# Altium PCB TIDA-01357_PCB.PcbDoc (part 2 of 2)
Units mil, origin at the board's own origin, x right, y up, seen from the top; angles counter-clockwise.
Board outline 1710 x 2300 mil, 4 copper layers (Top Layer, Mid Layer 1, Mid Layer 2, Bottom Layer), stack 79.8 mil thick; 69 components, 66 nets, 243 pads, 213 vias.
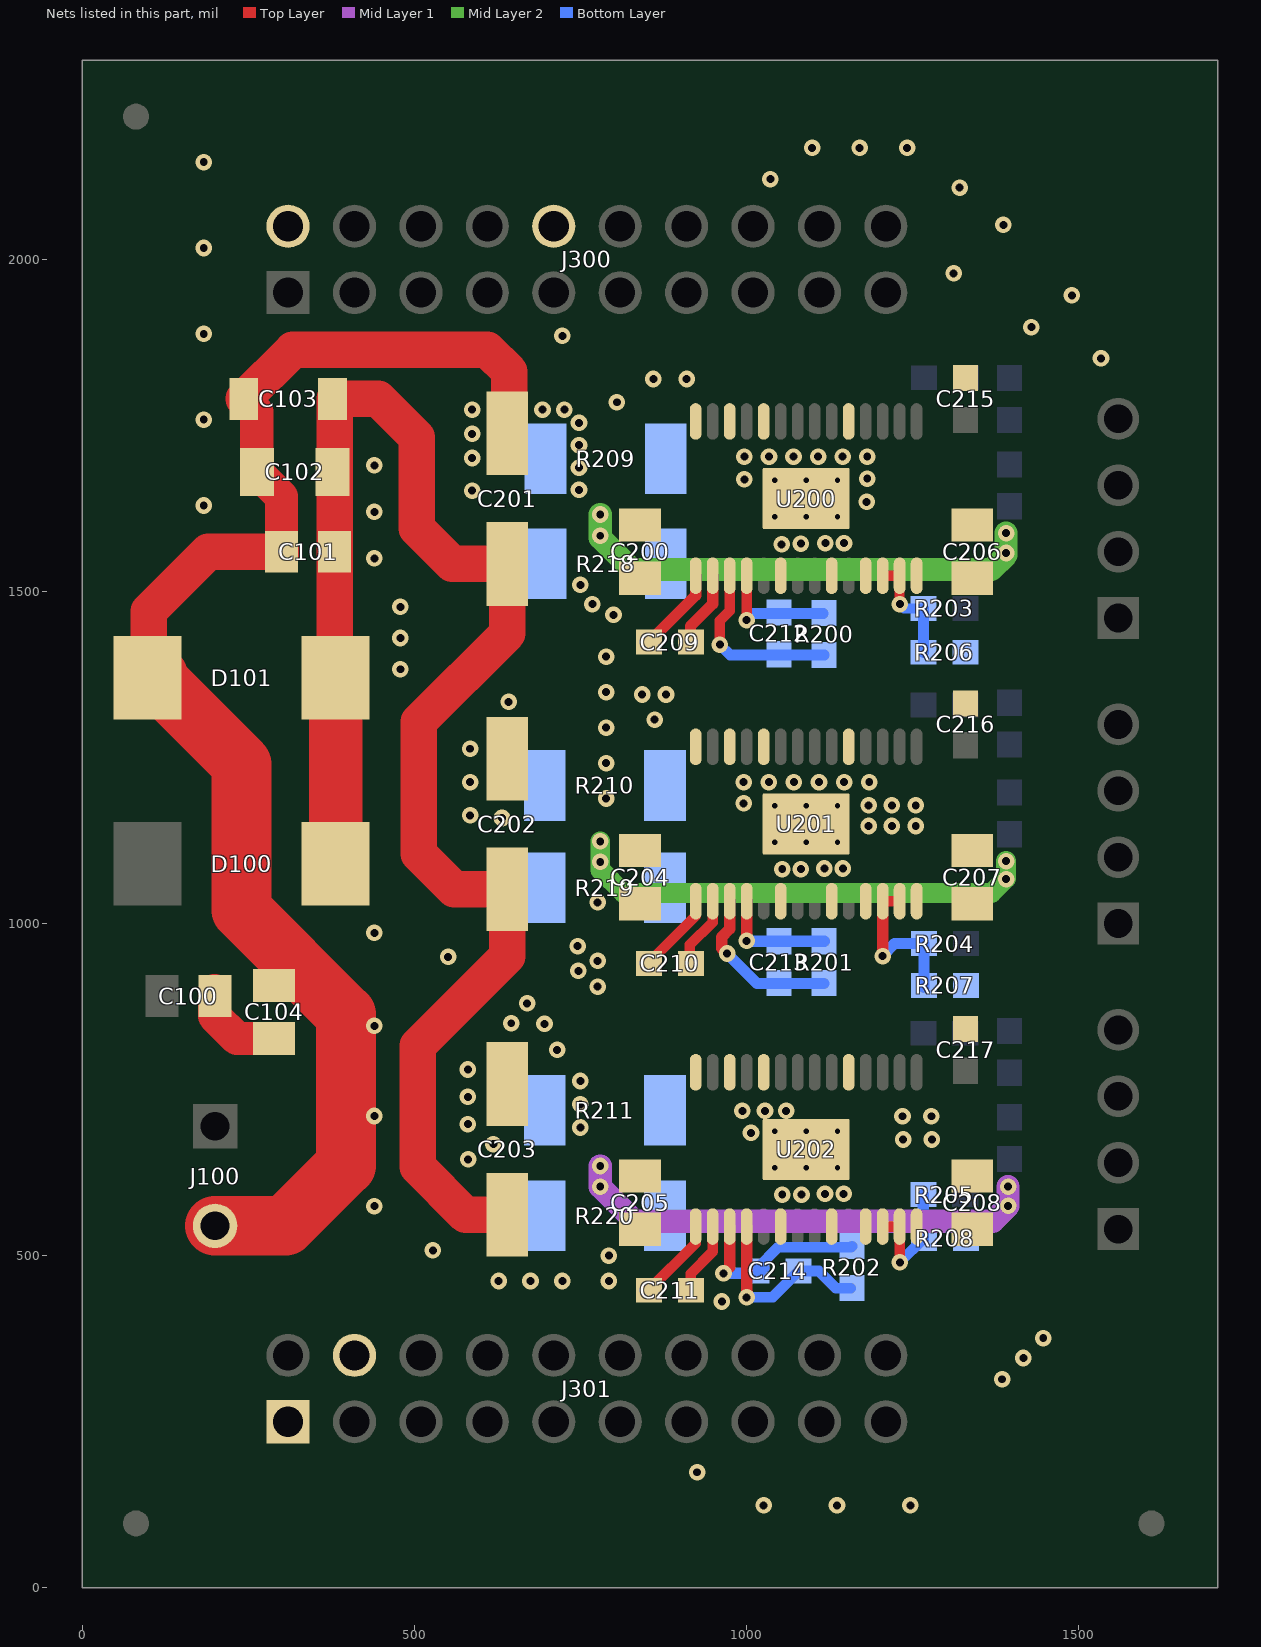
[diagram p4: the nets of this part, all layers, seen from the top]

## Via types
v1: diameter 25, hole 12, Top Layer to Bottom Layer, tented both sides, 195 vias
v2: diameter 19.68, hole 7.87, Top Layer to Bottom Layer, 18 vias

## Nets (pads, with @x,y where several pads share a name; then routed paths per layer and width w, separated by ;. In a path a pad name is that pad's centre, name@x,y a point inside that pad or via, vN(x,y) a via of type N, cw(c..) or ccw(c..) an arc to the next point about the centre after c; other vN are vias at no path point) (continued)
GND: C101.2 C102.2 C103.2 C104.2 C200.1 C201.2 C202.2 C203.2 C204.1 C205.2 C206.1 C207.1 C208.1 C215.2 C216.2 C217.2 D101.2 J100.2 J300.2 J301.4 R206.2 R207.2 R208.2 R209.2 R210.2 R211.2 R218.2 R219.2 R220.2 U200.14 U200.19 U200.24 U200.26 U200.28 U200.29 U201.14 U201.19 U201.24 U201.26 U201.28 U201.29 U202.14 U202.19 U202.24 U202.26 U202.28 U202.29 | length 2205.4
  Top Layer w50: C103.2@243.07,1790 262.91,1770.16 C102.2@262.91,1680 300,1642.91 C101.2@300,1560
  Top Layer w55: D101.2@100,1370 100,1470 190,1560 C101.2@300,1560 ; C103.2@243.07,1790 317.07,1864 610,1864 643,1831 C201.2@643,1760
  Top Layer w90: D101.2@110,1370 240,1240 240,1020 397,863 397,636 306,545 J100.2@200,545
  Top Layer w100: D101.2@98.27,1370 100,1370 D101.2@110,1370
  other v1: 1026,124 1136.5,124 1247,124 926,174 1385,314 1417,346 1447,376 963,431 627,462 675,462 723,462 793,462 793,500 528,508 440,574.67 581,645 619,668 1236,675 1279.4,675 1007,685 750,693 580.68,698 440,710.33 1235,710 1278.4,710 994,718 1028,718 1060,718 750,728 580.68,739.15 750,763 580.68,780.29 715,810 440,846 696,849 646,850 670,880 776,905 747,929 776,944 551,950 746,966 440,986 776,1032 1184,1147 1219,1147 1255,1147 632,1159 584.13,1163 1184,1178 1219,1178 1255,1178 996,1181 789,1188.32 584.13,1213.14 996,1213 1033.8,1213 1071.6,1213 1109.4,1213 1147.2,1213 1185,1213 789,1241.74 584.13,1263.29 789,1295.16 862,1307 642,1334 843,1345 879,1345 789,1348.58 479,1383 789,1402 479,1430 800,1465 479,1477 768,1481 750,1510 440,1550 440,1620 183,1629.5 1181,1635 587,1652 748,1653 997,1669 1182,1670 748,1686.67 440,1690 587,1701 997,1703 1034,1703 1071,1703 1108,1703 1145,1703 1182,1703 748,1720.33 587,1737.43 748,1754 183,1758.75 587,1773.86 693,1774 726,1773.86 805,1785 860,1820 910,1820 1534,1851 723,1885 183,1888 1429,1898 1490,1946 1312,1979 183,2017.25 1387,2052 1321,2108 1036,2121 183,2146.5 1099,2168 1170.5,2168 1242,2168
  other v2: 1042.76,632.44 1090,632.44 1137.24,632.44 1042.76,687.56 1090,687.56 1137.24,687.56 1042.76,1122.44 1090,1122.44 1137.24,1122.44 1042.76,1177.56 1090,1177.56 1137.24,1177.56 1042.76,1612.44 1090,1612.44 1137.24,1612.44 1042.76,1667.56 1090,1667.56 1137.24,1667.56
LP_+3V3: J301.1
LP_RESET: J300.10
NetC100_2: C100.2 C104.1 | length 142.1
  Top Layer w50: C100.2@199,899 199,861 233,827 C104.1@289,827
NetC209_1: C209.1 U200.1 | length 128.9
  Top Layer w17: C209.1@853.5,1424 923.66,1494.16 U200.1@923.66,1523.86
NetC209_2: C209.2 U200.2 | length 113.6
  Top Layer w17: C209.2@916,1424 916,1448 949.25,1481.25 U200.2@949.25,1523.86
NetC210_1: C210.1 U201.1 | length 122.1
  Top Layer w16: C210.1@853,941 923.66,1011.66 U201.1@923.66,1033.86
NetC210_2: C210.2 U201.2 | length 110
  Top Layer w16: C210.2@915,938 915,968 949.25,1002.25 U201.2@949.25,1033.86
NetC211_1: C211.1 U202.1 | length 126.5
  Top Layer w16: C211.1@852,447 923.66,518.66 U202.1@923.66,543.86
NetC211_2: C211.2 U202.2 | length 110.6
  Top Layer w16: C211.2@916,447 916,473 949.25,506.25 U202.2@949.25,543.86
NetC212_2: C212.2 R200.1 U200.3 | length 273.4
  Top Layer w16: v1(960,1420) 960,1456 974.84,1470.84 U200.3@974.84,1523.86
  Bottom Layer w16: v1(960,1420) 975.5,1404.5 R200.1@1117,1404.5
NetC213_2: C213.2 R201.1 U201.3 | length 252
  Top Layer w17: v1(971,955) 963,963 963,980 974.84,991.84 U201.3@974.84,1033.86
  Bottom Layer w6: R201.1@1116.56,910 R201.1@1117.07,910.5
  Bottom Layer w17: v1(971,955) 1016,910 R201.1@1116.56,910
NetC214_2: C214.2 R202.1 U202.3 | length 299.6
  Top Layer w17: v1(965.5,473.5) 974.84,482.84 U202.3@974.84,543.86
  Bottom Layer w16: C214.2@1015.5,477 1015.5,480.5 1048,513 1157.5,513 R202.1@1159,514.5
  Bottom Layer w17: v1(965.5,473.5) 1018.5,473.5 C214.2@1026.5,481.5
NetR203_2: R203.2 R206.1 U200.12 U200.13 | length 172.9
  Top Layer w15: v1@1230.75,1481 U200.13@1230.75,1523.86
  Top Layer w16: U200.12@1205.16,1523.86 U200.13@1230.75,1523.86
  Bottom Layer w15: v1(1231,1481) 1237.46,1474.54 R203.2@1266.75,1474.54
  Bottom Layer w17: R206.1@1266.75,1408.54 R203.2@1266.75,1474.54
NetR204_2: R204.2 R207.1 U201.12 U201.13 | length 245.2
  Top Layer w16: U201.12@1205.16,1033.86 U201.13@1230.75,1033.86
  Top Layer w17: v1(1205.16,951) U201.12@1205.16,1033.86
  Bottom Layer w6: R204.2@1267.35,970.16 R204.2@1267.5,970
  Bottom Layer w17: v1@1204.5,951.5 1223.16,970.16 R204.2@1267.35,970.16 ; R207.1@1267.5,904 R204.2@1267.5,970
NetR205_2: R205.2 R208.1 U202.12 U202.13 | length 196.6
  Top Layer w6: v1@1230.75,490.25 v1(1231,490)
  Top Layer w16: U202.12@1205.16,543.86 U202.13@1230.75,543.86 v1@1230.75,490.25
  Bottom Layer w6: R208.1@1266,525 R208.1@1266.5,525
  Bottom Layer w16: v1(1231,490) R208.1@1266,525
  Bottom Layer w17: R208.1@1266.5,525 R205.2@1266.5,592
NetR209_1: R209.1 U200.6
  other v1: 1053,1571 1082,1572
NetR210_1: R210.1 U201.6
  other v1: 1054,1082 1082,1082
NetR211_1: R211.1 U202.6
  other v1: 1054,592 1083,592
NetR218_1: R218.1 U200.9
  other v1: 1119,1573 1147,1573
NetR219_1: R219.1 U201.9
  other v1: 1117.38,1083 1145.38,1083
NetR220_1: R220.1 U202.9
  other v1: 1118.38,593 1146.38,593
V_SUPPLY: C101.1 C102.1 C103.1 C200.2 C201.1 C202.1 C203.1 C204.2 C205.1 C206.2 C207.2 C208.2 C212.1 C213.1 C214.1 D100.1 D101.1 R200.2 R201.2 R202.2 U200.4 U200.11 U201.4 U201.11 U202.4 U202.11 | length 5198.8
  Top Layer w6: C103.1@376.93,1790 C103.1@380,1790 ; C202.1@614.43,1051.57 C202.1@640,1051.57
  Top Layer w16: v1(1000.43,1457) U200.4@1000.43,1523.86
  Top Layer w17: v1(1000.43,437.43) U202.4@1000.43,543.86 ; v1(1000.43,974) U201.4@1000.43,1033.86
  Top Layer w55: D101.1@380,1370 C101.1@380,1560 380,1790 446,1790 504,1732 504,1595 557.43,1541.57 C201.1@640,1541.57 640,1437 507,1304 507,1105 560.43,1051.57 C202.1@614.43,1051.57 ; 505,634 577.43,561.57 C203.1@640,561.57 ; 505,637 505,816 640,951 C202.1@640,1051.57
  Top Layer w80: D100.1@381.73,1090 D101.1@381.73,1370
  Mid Layer 1 w35: v1(780,635) v1(780,604) 832,552 1371,552 v1(1394,575) v1(1394,604)
  Mid Layer 2 w30: v1(780,1124) v1(780,1093) 780,1081 815,1046 1369,1046 1391,1068 v1(1391,1094) ; v1@780,1581 v1(780,1584) ; v1@1391,1555 v1(1391,1558)
  Mid Layer 2 w35: v1@780,1581 828,1533 1369,1533 v1@1391,1555 ; v1(780,1584) v1(780,1616) ; v1(1391,1558) v1(1391,1588)
  Bottom Layer w16: v1(1000.43,437.43) 1039.43,437.43 1079,477 1109,477 1135,451 R202.2@1157,451 ; v1(1000.43,1457) 1010.43,1467 R200.2@1116,1467
  Bottom Layer w17: v1@1000,973.5 R201.2@1117.07,973.5
  other v1: 1391,1067
pads on no net: FID1.1 FID2.1 FID3.1 J300.12 J300.14 J301.2 J301.3 J301.5 J301.6 J301.7 J301.8 J301.10 J301.11 J301.12 J301.14 J301.16 J301.18 J301.20 LBL1.0

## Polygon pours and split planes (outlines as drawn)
GND on Top Layer "Top Layer-No Net 1" (solid, remove dead copper, pour order 46): 0,0 1710,0 1710,2300 0,2300 0,0
NetR220_1 on Top Layer "TOP_LAYER_NETR220_1_P026" (solid, remove dead copper, pour order 26): 1118,516 1139.38,516 1139.38,573 1145.38,579 1159.38,579 1161.38,581 1161.38,602 1157.38,606 1102.38,606 1102.38,586 1118,570.38
NetR219_1 on Top Layer "TOP_LAYER_NETR219_1_P024" (solid, remove dead copper, pour order 24): 1117,1006 1138.38,1006 1138.38,1063 1144.38,1069 1158.38,1069 1160.38,1071 1160.38,1092 1156.38,1096 1101.38,1096 1101.38,1076 1117,1060.38
NetR218_1 on Top Layer "TOP_LAYER_NETR218_1_P020" (solid, remove dead copper, pour order 20): 1119,1496 1140,1496 1140,1553 1146,1559 1160,1559 1162,1561 1162,1582 1157,1587 1103,1587 1103,1566 1119,1550 1119,1540
NetR211_1 on Top Layer "Top Layer-No Net" (solid, remove dead copper, pour order 18): 1040.15,517 1062.15,517 1062.15,575 1066.15,579 1091,579 1097,585 1097,600 1091,606 1044.15,606 1040.15,602
NetR210_1 on Top Layer "Top Layer-No Net" (solid, remove dead copper, pour order 16): 1040.15,1007 1062.15,1007 1062.15,1065 1066.15,1069 1090,1069 1096,1075 1096,1090 1090,1096 1044.15,1096 1040.15,1092
NetR209_1 on Top Layer "Top Layer-No Net" (solid, remove dead copper, pour order 14): 1040,1496 1062,1496 1062,1551 1070,1559 1091,1559 1096,1564 1096,1581 1091,1586 1045,1586 1040,1581
V_SUPPLY on Top Layer "TOP_LAYER_V_SUPPLY_P000" (solid, remove dead copper, pour order 0): 1170,1500 1180,1500 1190,1500 1190,1550 1210,1570 1360,1570 1380,1550 1390,1540 1400,1540 1410,1550 1410,1600 1390,1630 1290,1630 1270,1610 1200,1610 1170,1580
V_SUPPLY on Top Layer "TOP_LAYER_V_SUPPLY_P002" (solid, pour order 2): 990,1500 1010,1500 1010,1560 1010,1580 990,1600 980,1610 907.24,1610 887.24,1630 690,1630 670,1610 610,1610 600,1600 600,1480 610,1470 670,1470 680,1480 680,1540 710,1570 970,1570 990,1550 990,1500
V_SUPPLY on Top Layer "TOP_LAYER_V_SUPPLY_P004" (solid, remove dead copper, pour order 4): 990,1010 1010,1010 1010,1070 1010,1090 990,1110 980,1120 907.24,1120 887.24,1140 690,1140 670,1120 610,1120 600,1110 600,990 610,980 670,980 680,990 680,1050 710,1080 970,1080 990,1060 990,1010
V_SUPPLY on Top Layer "TOP_LAYER_V_SUPPLY_P006" (solid, remove dead copper, pour order 6): 1170,1010 1180,1010 1190,1010 1190,1060 1210,1080 1360,1080 1390,1050 1400,1050 1410,1060 1410,1110 1390,1140 1290,1140 1270,1120 1200,1120 1170,1090
V_SUPPLY on Top Layer "TOP_LAYER_V_SUPPLY_P008" (solid, remove dead copper, pour order 8): 1170,520 1180,520 1190,520 1190,570 1210,590 1360,590 1390,560 1400,560 1410,570 1410,610 1390,650 1290,650 1270,630 1200,630 1170,600
V_SUPPLY on Top Layer "TOP_LAYER_V_SUPPLY_P010" (solid, remove dead copper, pour order 10): 990,520 1010,520 1010,580 1010,600 990,620 980,630 907.24,630 887.24,650 690,650 670,630 610,630 600,620 600,500 610,490 670,490 680,500 680,560 710,590 970,590 990,570 990,520
GND on Bottom Layer "Top Layer-No Net 1" (solid, remove dead copper, pour order 48): 0,0 1710,0 1710,2300 0,2300 0,0
NetR218_1 on Bottom Layer "BOTTOM_LAYER_NETR218_1_P030" (solid, remove dead copper, pour order 30): 1110,1590 1160,1590 1170,1580 1170,1560 1120,1510 1006,1510 976,1480 850,1480 840,1490 840,1590 840,1591 850,1601 949,1601 1007,1543 1092,1543 1100,1551 1100,1580
NetR209_1 on Bottom Layer "BOTTOM_LAYER_NETR209_1_P028" (solid, remove dead copper, pour order 28): 1036,1593 1083,1593 1096,1580 1096,1565 1083,1552 1014,1552 936,1630 850,1630 840,1640 840,1750 850,1760 930.11,1760 960,1729.78 960,1669
NetR210_1 on Bottom Layer "BOTTOM_LAYER_NETR210_1_P032" (solid, remove dead copper, pour order 32): 1036,1103 1083,1103 1096,1090 1096,1075 1083,1062 1014,1062 936,1140 850,1140 840,1150 840,1260 850,1270 930.11,1270 960,1239.78 960,1179
NetR219_1 on Bottom Layer "BOTTOM_LAYER_NETR219_1_P034" (solid, remove dead copper, pour order 34): 1108.38,1100 1158.38,1100 1168.38,1090 1168.38,1070 1118.38,1020 1004.38,1020 974.38,990 848.38,990 838.38,1000 838.38,1100 838.38,1101 848.38,1111 947.38,1111 1005.38,1053 1090.38,1053 1098.38,1061 1098.38,1090
NetR211_1 on Bottom Layer "BOTTOM_LAYER_NETR211_1_P038" (solid, remove dead copper, pour order 38): 1037,613 1084,613 1097,600 1097,585 1084,572 1015,572 937,650 851,650 841,660 841,770 851,780 931.11,780 961,749.78 961,689
NetR220_1 on Bottom Layer "BOTTOM_LAYER_NETR220_1_P040" (solid, remove dead copper, pour order 40): 1109.38,610 1159.38,610 1169.38,600 1169.38,580 1119.38,530 1005.38,530 975.38,500 849.38,500 839.38,510 839.38,610 839.38,611 849.38,621 948.38,621 1006.38,563 1091.38,563 1099.38,571 1099.38,600

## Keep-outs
Keep-Out Layer:
  text ".Layer_Name" at -1713,-1458.49 h60

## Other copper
Top Layer:
  text ".Layer_Name" at -1713,-1458.49 h60
Bottom Layer:
  text ".Layer_Name" at -1713,-1458.49 h60

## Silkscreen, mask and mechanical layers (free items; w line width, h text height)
Top Overlay:
  region: 1659,2237 1359,2237 1359,2137 1659,2137
  text "TIDA-01357 PCB_Rev-E1" at 231,2171 h40
  text ".Layer_Name" at -1713,-1458.49 h60
Bottom Overlay:
  text ".Layer_Name" at -1713,-1458.49 h60
Top Paste:
  text ".Layer_Name" at -1713,-1458.49 h60
Bottom Paste:
  text ".Layer_Name" at -1713,-1458.49 h60
Top Solder:
  text ".Layer_Name" at -1713,-1458.49 h60
  text ".Layer_Name" at -1713,-1458.49 h60
Bottom Solder:
  text ".Layer_Name" at -1713,-1458.49 h60
Drill Guide:
  text ".Layer_Name" at -1713,-1458.49 h60
M1 Board Outline:
  the board outline again, w10
  text ".Layer_Name" at -1713,-1458.49 h60
M2 Board Dimensions:
  rectangle: -2290,-875 -2165,-750
  rectangle: -2165,-1000 -1790,-875
  lines w7: -2290,-875 -1290,-875 ; -2165,-1000 -2165,-750 ; -2040,-1000 -2040,-750 ; -1790,-1000 -1790,-750 ; -1540,-1000 -1540,-750 ; -2290,-1000 -1290,-1000 -1290,-750 -2290,-750 -2290,-1000
  text ".Layer_Name" at -1713,-1458.49 h60
M3 3D STEP Top:
  text ".Layer_Name" at -1713,-1458.49 h60
M4 3D STEP Bottom:
  text ".Layer_Name" at -1713,-1458.49 h60
M5 Assembly Top:
  lines w10: -2582,-1530.17 4018,-1530.17 ; -2582,-1326.83 4020,-1326.83 ; -2582,-1123.5 -2582,-1733.5 1423,-1733.5 4020,-1733.5 4020,-1123.5 -2581.5,-1123.5 -2581.5,-1733.5 -1006,-1733.5 ; -117,-1733.5 -117,-1123.5 ; 1150,-1326.83 1150,-1123.5 ; 1990,-1326.83 1990,-1123.5 ; 2612,-1740 2612,-1537.17
  text "COMPONENTS MARKED 'DNP' SHOULD NOT BE POPULATED." at -1136.5,-918.5 h60
  text "ASSEMBLY VARIANT:" at -1137,-1034 h60
  text ".VariantName" at -101,-1034 h60
  text "PCB VIEWED FROM TOP SIDE" at -2518.5,-1255.67 h60
  text "BOARD #:" at -42,-1255.67 h60
  text ".PRJ_Number" at 503.5,-1255.67 h60
  text "REV:" at 1348,-1255.67 h60
  text ".PCB_Rev" at 1639.5,-1255.67 h60
  text "SVN REV:" at 2186,-1255.67 h60
  text ".VersionControl_RevNumber" at 2692,-1255.67 h60
  text "TID #:" at -42,-1459 h60
  text ".TID" at 503.5,-1459 h60
  text "PLOT NAME =" at -2518.5,-1664.34 h60
  text ".plot_File_Name" at -1713,-1664.34 h60
  text "GENERATED    :" at -40,-1664.34 h60
  text ".Print_Date" at 829.5,-1664.34 h60
  text ".Print_Time" at 1558.5,-1664.34 h60
  text "TEXAS INSTRUMENTS" at 2823,-1664.34 h60
M6 Assembly Bottom:
  lines w10: -2582.5,-1327.33 4019.5,-1327.33 ; -2580.5,-1530.67 4019.5,-1530.67 ; -1174.5,-1740.5 -1174.5,-1537.67 ; -552.5,-1327.33 -552.5,-1124 ; 287.5,-1327.33 287.5,-1124 ; 1554.5,-1734 1554.5,-1124 ; 2443.5,-1734 4019,-1734 4019,-1124 -2582.5,-1124 -2582.5,-1734 14.5,-1734 4019.5,-1734 4019.5,-1124
  text "COMPONENTS MARKED 'DNP' SHOULD NOT BE POPULATED." at 3812,-918 h60
  text ".VariantName" at 2768,-1034 h60
  text "ASSEMBLY VARIANT:" at 3807,-1034 h60
  text ".VersionControl_RevNumber" at -1254.5,-1256.17 h60
  text "SVN REV:" at -748.5,-1256.17 h60
  text ".PCB_Rev" at -202,-1256.17 h60
  text "REV:" at 89.5,-1256.17 h60
  text ".PRJ_Number" at 934,-1256.17 h60
  text "BOARD #:" at 1479.5,-1256.17 h60
  text "PCB VIEWED FROM BOTTOM SIDE" at 3956,-1256.17 h60
  text ".TID" at 934,-1459.5 h60
  text "TID #:" at 1479.5,-1459.5 h60
  text "TEXAS INSTRUMENTS" at -1385.5,-1664.84 h60
  text ".Print_Time" at -121,-1664.84 h60
  text ".Print_Date" at 608,-1664.84 h60
  text "GENERATED    :" at 1477.5,-1664.84 h60
  text ".plot_File_Name" at 3150.5,-1664.84 h60
  text "PLOT NAME =" at 3956,-1664.84 h60
M9 Title Sheet:
  drawing of 57 lines, arcs and shapes, not listed
  text "1" at -1550.16,7436.5 h70
  text "2" at 945.5,7436.5 h70
  text "3" at 3434.84,7436.5 h70
  text "4" at 5941.51,7436.5 h70
  text "5" at 8440.5,7436.5 h70
  text "6" at 10945.5,7436.5 h70
  text "A" at -2706.5,6293.5 h70
  text "A" at 12093.5,6293.5 h70
  text "B" at -2706.5,3913.5 h70
  text "B" at 12093.5,3913.5 h70
  text "C" at -2706.5,1538.5 h70
  text "C" at 12093.5,1538.5 h70
  text "PROJECT TITLE:" at 9053.5,-322.5 h45
  text ".PRJ_Title" at 9103.5,-455.83 h70
  text "DESIGNED FOR:" at 9053.5,-623.5 h45
  text ".PRJ_Customer" at 9103.5,-763.5 h70
  text "D" at -2706.5,-831.5 h70
  text "D" at 12093.5,-831.5 h70
  text "FILE NAME:" at 9053.5,-923.5 h45
  text ".PCB_File_Name_No_Path" at 9103.5,-1043.5 h70
  text "Texas Instruments (TI) and/or its licensors do not warrant the accuracy or completeness of this specification" at 4084,-1205.34 h45
  text "ENGINEER:" at 9053.5,-1213.5 h45
  text "LAYOUT BY:" at 10558.5,-1213.5 h45
  text "or any information contained therein. TI and/or its licensors do not warrant that this design will meet" at 4039.01,-1318 h45
  text ".PRJ_Engineer" at 9103.5,-1368.49 h70
  text ".PCB_Layout" at 10609,-1368.49 h70
  text "the specifications, will be suitable for your application or fit for any particular purpose, or will operate in" at 4039.01,-1430.67 h45
  text ".Layer_Name" at -1713,-1458.49 h60
  text "ALTIUM DESIGNER VERSION:" at 10558.5,-1523.5 h45
  text "an implementation. TI and/or its licensors do not warrant that the design is production worthy. You should" at 4039.01,-1543.33 h45
  text "completely validate and test your design implementation to confirm the system functionality for your application." at 4084,-1656 h45
  text ".print_Scale" at 9103.5,-1656.83 h70
  text ".Application_BuildNumber" at 10609,-1656.83 h70
  text "1" at -1550.16,-1863.5 h70
  text "2" at 945.5,-1863.5 h70
  text "3" at 3434.84,-1863.5 h70
  text "4" at 5941.51,-1863.5 h70
  text "5" at 8440.5,-1863.5 h70
  text "6" at 10945.5,-1863.5 h70
M10 Fab Notes:
  drawing of 173 lines, arcs and shapes, not listed
  text "DESIGN INFORMATION" at 10088.02,5601 h60
  text "MIN. TRACK WIDTH:" at 9443.46,5421 h60
  text "8" at 10539.7,5421 h60
  text "MIL" at 10694.46,5421 h60
  text "MIN. CLEARANCE:" at 9443.46,5289 h60
  text "0.2" at 10479.7,5289 h60
  text "mm" at 10694.46,5289 h60
  text "MIN. VIA PAD SIZE:" at 9443.46,5157 h60
  text "24" at 10509.71,5157 h60
  text "MIL" at 10694.46,5157 h60
  text "0.05mm (2MIL)" at 10138.46,5015.29 h60
  text "MINIMUM ANNULAR RING" at 9114.23,5011 h60
  text "EXTERNAL" at 10846.46,5011 h60
  text "PER" at 9314.23,4893 h60
  text "IPC-D-275 CLASS 2 LEVEL C" at 9534.23,4893 h60
  text "MIL, HOLES" at 11022.46,4780.71 h60
  text "+/-" at 10630,4780 h60
  text "+/-" at 11484,4780 h60
  text "REGISTRATION TOLERANCES:" at 9114.23,4775 h60
  text "METAL" at 10314,4775 h60
  text "5" at 10890.2,4775 h60
  text "3" at 11723.2,4775 h60
  text "MIL" at 11839.46,4775 h60
  text "+/-" at 11484,4662 h60
  text "HOLE SIZE TOLERANCE (UNLESS OTHERWISE SPECIFIED):" at 9114.23,4657 h60
  text "3" at 11723.2,4657 h60
  text "MIL" at 11839.46,4657 h60
  text "MATERIAL:" at 9039.46,4447.54 h60
  text "FR-4 High Tg" at 10025.9,4307.21 h60
  text "FR-408" at 9460.46,4298.64 h60
  text "OTHER" at 10948.46,4298.64 h60
  text "X" at 9871,4295 h60
  text "62 MIL (1.6mm) +/-10%" at 9780.56,4135.92 h60
  text "THICKNESS:" at 9114.23,4131.64 h60
  text "X" at 9652.4,4131.64 h60
  text "OTHER" at 11065.46,4131.64 h60
  text "TOLERANCE:" at 9114.23,3973.64 h60
  text "X" at 9953.53,3973.64 h60
  text "ANSI IPC-6012 TYPE 3 CLASS 2" at 10140.48,3973.64 h60
  text "OTHER +/-" at 10140.46,3817.64 h60
  text "BOW & TWIST:" at 9114.23,3660.64 h60
  text "X" at 9953.53,3660.64 h60
  text "ANSI IPC-6012 TYPE 3 CLASS 2" at 10140.48,3660.64 h60
  text "OTHER +/-" at 10140.46,3502.13 h60
  text "DRILLING:" at 9039.46,3363.64 h60
  text "REFERENCE:" at 9114.23,3246.64 h60
  text "X" at 9762.46,3246.64 h60
  text "AS SHOWN" at 9949.46,3246.64 h60
  text "X" at 10663.46,3246.64 h60
  text "NC_DRILL FILES" at 10800.46,3246.64 h60
  text "PTH COPPER THICKNESS:" at 9114.23,3088.64 h60
  text "X" at 10244.46,3088.64 h60
  text "20-30 um" at 10381.46,3088.64 h60
  text "OTHER" at 11098.46,3088.64 h60
  text "BOARD FINISH:" at 9039.46,2929.64 h60
  text "SILKSCREEN:" at 9194.68,2811.64 h60
  text "X" at 10143.46,2811.64 h60
  text "TOP" at 10269.46,2811.64 h60
  text "X" at 10653.46,2811.64 h60
  text "BOTTOM" at 10780.46,2811.64 h60
  text "SILKSCREEN COLOR:" at 9194.68,2644.64 h60
  text "X" at 10142.42,2644.64 h60
  text "WHITE" at 10269.46,2644.64 h60
  text "OTHER" at 10780.46,2644.64 h60
  text "X" at 10273.42,2485.44 h60
  text "GREEN" at 10400.46,2485.44 h60
  text "OTHER" at 11018.46,2485.44 h60
  text "SOLDER RESIST COLOR:" at 9194.68,2474.64 h60
  text "X" at 10273.42,2315.44 h60
  text "MATTE" at 10400.46,2315.44 h60
  text "SEMI-GLOSS" at 11018,2314.8 h60
  text "IMMERSION GOLD (ENIG)" at 10100.46,2126.92 h60
  text "ENEPIG" at 11438,2123.64 h60
  text "SURFACE FINISH:" at 9039.46,2122.64 h60
  text "X" at 9913.51,2122.64 h60
  text "IMM. TIN/SILVER OR EQUIV" at 9369,1965.64 h60
  text "OTHER" at 10800.46,1965.64 h60
  text "ARRAY/PANEL:" at 9039.46,1786.64 h60
  text "CUT AND TRIM PER M1 BOARD OUTLINE" at 10100.46,1782.35 h60
  text "N.C. ROUTE" at 10100.46,1630.64 h60
  text "X" at 10779.46,1630.64 h60
  text "V. SCORE" at 10966.46,1630.64 h60
  text "CERTIFICATION:" at 9039.46,1493.64 h60
  text "MATERIALS AND WORKMANSHIP FOR ALL PCBS" at 9764.46,1493.64 h60
  text "TO MEET OR EXCEED THE REQUIREMENTS OF:" at 9764.46,1395.64 h60
  text "X" at 9390.96,1259.13 h60
  text "ANSI IPC-A-600F CLASS ->" at 9529.96,1259.13 h60
  text "X" at 11169.02,1259.13 h60
  text "2" at 11287.96,1259.14 h60
  text "1" at 10972.96,1257.64 h60
  text "3" at 11641.96,1257.64 h60
  text "X" at 10205.02,1099.64 h60
  text "RoHS" at 10341.96,1099.64 h60
  text "OTHER" at 10986.36,1099.64 h60
  text "PER ORDER" at 11383.42,1099.64 h60
  text "ALL BOARDS MUST MEET OR EXCEED UL94-V0 REQUIREMENTS." at 9067,934 h60
  text "PCB MUST BEAR THE UL94V-0 UL REGISTERED MATERIAL ID NUMBER" at 9067,814 h60
  text "ADDITIONAL REQUIREMENTS:" at 9039.46,640.64 h60
  text "MICROSECTION:" at 9114.23,525.64 h60
  text "YES" at 10019.96,525.64 h60
  text "REQUIRED" at 10881.46,369.49 h60
  text "BARE BOARD ELEC. TEST:" at 9114.23,366.64 h60
  text "NONE" at 10419.96,366.64 h60
  text "X" at 10754.46,366.64 h60
  text "PER ORDER" at 11473.46,366.64 h60
  text ".Layer_Name" at -1713,-1458.49 h60
M11 Gerber Information:
  lines w10: -2582,-1530.17 4018,-1530.17 ; -2582,-1326.83 4020,-1326.83 ; -2582,-1123.5 -2582,-1733.5 1423,-1733.5 4020,-1733.5 4020,-1123.5 -2581.5,-1123.5 -2581.5,-1733.5 -1006,-1733.5 ; -117,-1733.5 -117,-1123.5 ; 1150,-1326.83 1150,-1123.5 ; 1990,-1326.83 1990,-1123.5 ; 2612,-1740 2612,-1537.17
  text "ALL ARTWORK VIEWED FROM TOP SIDE" at -2518.5,-1255.67 h60
  text "BOARD #:" at -42,-1255.67 h60
  text ".PRJ_Number" at 503.5,-1255.67 h60
  text "REV:" at 1348,-1255.67 h60
  text ".PCB_Rev" at 1639.5,-1255.67 h60
  text "SVN REV:" at 2186,-1255.67 h60
  text ".VersionControl_RevNumber" at 2692,-1255.67 h60
  text "LAYER NAME =" at -2518.5,-1458.49 h60
  text "TID #:" at -42,-1459 h60
  text ".TID" at 503.5,-1459 h60
  text "PLOT NAME =" at -2518.5,-1664.34 h60
  text ".plot_File_Name" at -1713,-1664.34 h60
  text "GENERATED    :" at -40,-1664.34 h60
  text ".Print_Date" at 829.5,-1664.34 h60
  text ".Print_Time" at 1558.5,-1664.34 h60
  text "TEXAS INSTRUMENTS" at 2823,-1664.34 h60
M12 Stackup:
  drawing of 191 lines, arcs and shapes, not listed
  text "Layer" at 7500.34,7230 h60
  text "Name" at 7910.26,7230 h60
  text "Material" at 8840,7230 h60
  text "Thickness" at 9699.77,7230 h60
  text "Constant" at 10349.6,7230 h60
  text "Board Layer Stack" at 10919.46,7230 h60
  text "1" at 7500.34,7110 h60
  text "Top Overlay" at 7910.26,7110 h60
  text "2" at 7500.34,6990 h60
  text "Top Solder" at 7910.26,6990 h60
  text "Solder Resist" at 8840,6990 h60
  text "0.40mil" at 9699.77,6990 h60
  text "3.5" at 10349.6,6990 h60
  text "3" at 7500.34,6870 h60
  text "Top Layer" at 7910.26,6870 h60
  text "Copper" at 8840,6870 h60
  text "1.40mil" at 9699.77,6870 h60
  text "4" at 7500.34,6750 h60
  text "Dielectric1" at 7910.26,6750 h60
  text "FR-4" at 8840,6750 h60
  text "59.20mil" at 9699.77,6750 h60
  text "4.8" at 10349.6,6750 h60
  text "5" at 7500.34,6630 h60
  text "Bottom Layer" at 7910.26,6630 h60
  text "Copper" at 8840,6630 h60
  text "1.40mil" at 9699.77,6630 h60
  text "6" at 7500.34,6510 h60
  text "Bottom Solder" at 7910.26,6510 h60
  text "Solder Resist" at 8840,6510 h60
  text "0.40mil" at 9699.77,6510 h60
  text "3.5" at 10349.6,6510 h60
  text "7" at 7500.34,6390 h60
  text "Bottom Overlay" at 7910.26,6390 h60
  text ".Layer_Name" at -1713,-1458.49 h60
M13 Component Bodies Top:
  text ".Layer_Name" at -1713,-1458.49 h60
M14 Component Bodies Bottom:
  text ".Layer_Name" at -1713,-1458.49 h60
M15 Courtyards Top:
  text ".Layer_Name" at -1713,-1458.49 h60
M16 Courtyards Bottom:
  text ".Layer_Name" at -1713,-1458.49 h60
Drill Drawing:
  circle w10: c3058.9,2603.16 r13.28
  circle w10: c3058.9,2603.16 r22.14
  lines w10: 3036.76,2392.84 3047.83,2392.84 3047.83,2381.77 3069.97,2381.77 3069.97,2392.84 3081.04,2392.84 3081.04,2414.98 3069.97,2414.98 3069.97,2426.05 3047.83,2426.05 3047.83,2414.98 3036.76,2414.98 3036.76,2392.84 ; 3036.76,2481.4 3081.04,2481.4 3081.04,2525.67 3036.76,2525.67 3036.76,2481.4 ; 3036.76,2724.92 3081.04,2724.92 3058.9,2680.64 3036.76,2724.92
  lines w12: 2996,2351.89 6108.94,2351.89 ; 2996,2750.38 6108.94,2750.38 ; 3311.63,2252.27 3311.63,2850 ; 3628.82,2252.27 3628.82,2850 ; 4250.56,2252.27 4250.56,2850 ; 4494.88,2252.27 4494.88,2850 ; 4855.22,2252.27 4855.22,2850 ; 5564.73,2252.27 5564.73,2850 ; 2996,2252.27 6108.94,2252.27 6108.94,2850 2996,2850 2996,2252.27
  text "Symbol" at 3055.77,2780.26 h72
  text "Quantity" at 3341.52,2780.26 h72
  text "Finished Hole Size" at 3658.7,2780.26 h72
  text "Plated" at 4280.45,2780.26 h72
  text "Hole Type" at 4524.77,2780.26 h72
  text "Drill Layer Pair" at 4885.11,2780.26 h72
  text "Hole Tolerance" at 5594.62,2780.26 h72
  text "18" at 3341.52,2680.64 h60
  text "7.87mil (0.200mm)" at 3658.7,2680.64 h60
  text "PTH" at 4280.45,2680.64 h60
  text "Round" at 4524.77,2680.64 h60
  text "Top Layer - Bottom Layer" at 4885.11,2680.64 h60
  text "195" at 3341.52,2581.02 h60
  text "12.00mil (0.305mm)" at 3658.7,2581.02 h60
  text "PTH" at 4280.45,2581.02 h60
  text "Round" at 4524.77,2581.02 h60
  text "Top Layer - Bottom Layer" at 4885.11,2581.02 h60
  text "14" at 3341.52,2481.4 h60
  text "43.31mil (1.100mm)" at 3658.7,2481.4 h60
  text "PTH" at 4280.45,2481.4 h60
  text "Round" at 4524.77,2481.4 h60
  text "Top Layer - Bottom Layer" at 4885.11,2481.4 h60
  text "40" at 3341.52,2381.77 h60
  text "45.28mil (1.150mm)" at 3658.7,2381.77 h60
  text "PTH" at 4280.45,2381.77 h60
  text "Round" at 4524.77,2381.77 h60
  text "Top Layer - Bottom Layer" at 4885.11,2381.77 h60
  text "267 Total" at 3341.52,2282.15 h60
  text ".Layer_Name" at -1713,-1458.49 h60
M17 Embedded Cavity:
  text ".Layer_Name" at -1713,-1458.49 h60
M18 Embedded Assembly:
  text ".Layer_Name" at -1713,-1458.49 h60
M19 Embedded Keepout:
  text ".Layer_Name" at -1713,-1458.49 h60
Mechanical 27:
  lines w10: 333,5697 333,6727
  lines w12: -717,4587 2183,4587 2183,6887 -717,6887 -717,4587

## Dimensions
-2290,-1000 to -1290,-1000 on M2 Board Dimensions
0,2300 to 0,0 on M2 Board Dimensions
0,2300 to 1710,2300 on M2 Board Dimensions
